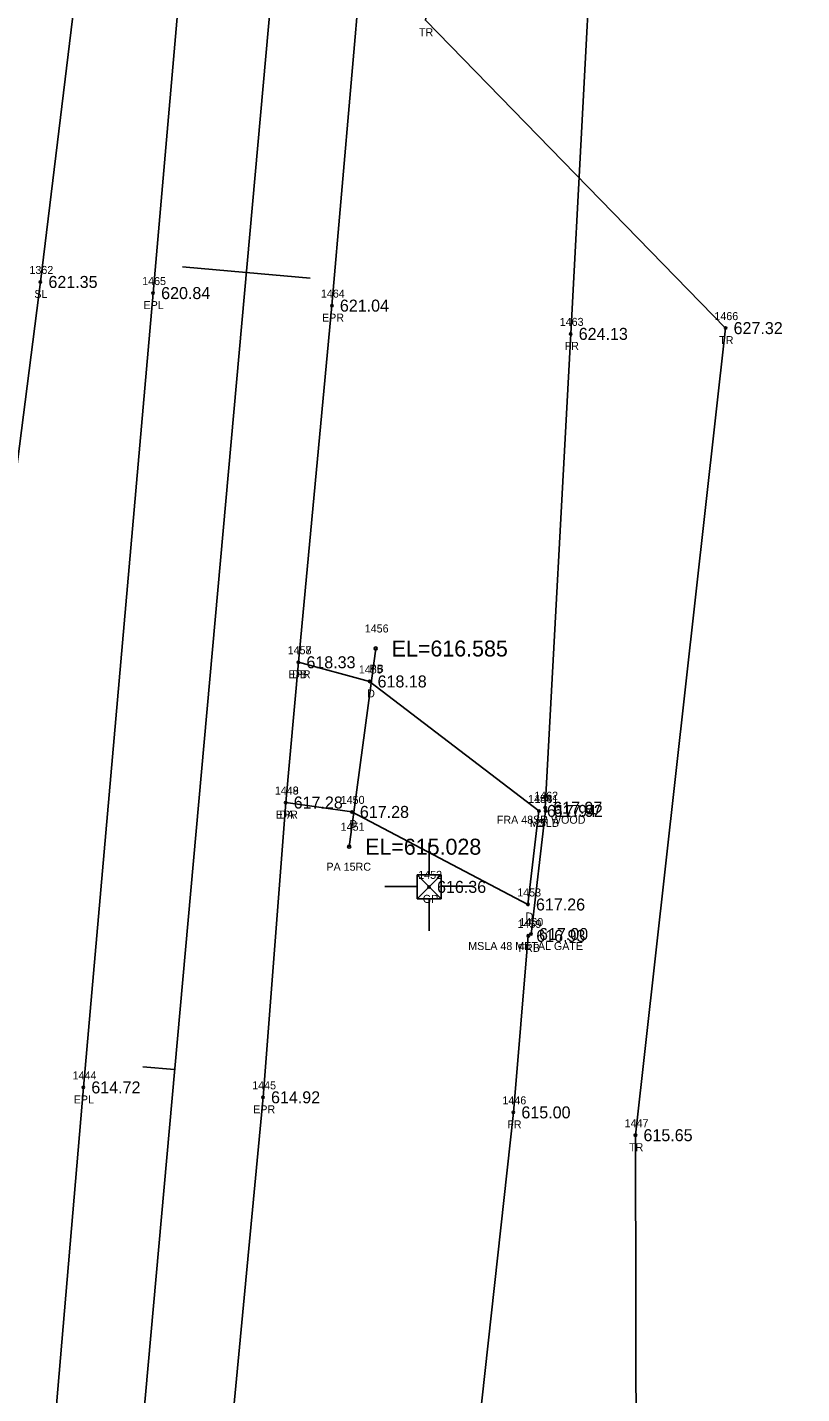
# Model space of a CAD drawing. Extents: x 1694813 to 1696862, y 1086485 to 1091027.
# Drawn here: x 1695817 to 1695913.8, y 1089981.5 to 1090152.3 of the extents above; entities that cross this region are included whole.
import ezdxf

# ---------------------------------------------------------------- set-up
doc = ezdxf.new("R2010")
doc.units = 0
for name, color, linetype in [('RD_EX_DR_Pipe', 7, 'Continuous'), ('RD_EX_DR_Pipe_txCode', 7, 'Continuous'), ('RD_EX_Driveway', 7, 'Continuous'), ('RD_EX_Driveway_txCode', 7, 'Continuous'), ('RD_EX_Fence_Other', 7, 'Continuous'), ('RD_EX_Fence_Other_txCode', 7, 'Continuous'), ('RD_EX_Misc', 7, 'Continuous'), ('RD_EX_Misc_txCode', 7, 'Continuous'), ('RD_EX_Road', 7, 'Continuous'), ('RD_EX_Road_txCode', 7, 'Continuous'), ('RD_EX_TX_Driveway_ELEV', 7, 'Continuous'), ('RD_EX_TX_Fence_Other_ELEV', 7, 'Continuous'), ('RD_EX_TX_Misc_ELEV', 7, 'Continuous'), ('RD_EX_TX_Road_ELEV', 7, 'Continuous'), ('RD_EX_TX_UT_ELEV', 7, 'Continuous'), ('RD_EX_TX_VEG_ELEV', 7, 'Continuous'), ('RD_EX_UT', 7, 'Continuous'), ('RD_EX_UT_txCode', 7, 'Continuous'), ('RD_EX_VEG', 7, 'Continuous'), ('RD_EX_VEG_txCode', 7, 'Continuous'), ('RD_HC_Cl', 7, 'Continuous'), ('RD_HC_Data_Tic', 7, 'Continuous'), ('RD_SMD_Locator', 7, 'Continuous'), ('RD_TX_Pipe_ElevEX', 7, 'Continuous')]:
    doc.layers.add(name, color=color, linetype=linetype)

msp = doc.modelspace()

# ---------------------------------------------------------------- linework, layer by layer
at = {"layer": 'RD_EX_DR_Pipe'}
msp.add_line((1695857.25, 1090049.87), (1695860.57, 1090074.64), dxfattribs=at)
at = {"layer": 'RD_EX_Driveway'}
msp.add_lwpolyline([(1695849.32, 1090055.39), (1695857.59, 1090054.22), (1695879.59, 1090042.65), (1695880.96, 1090054.34), (1695859.8, 1090070.52), (1695850.91, 1090072.92)], dxfattribs=at)
at = {"layer": 'RD_EX_Fence_Other'}
for points in [[(1695881.74, 1090054.74), (1695884.93, 1090113.96), (1695890.45, 1090217.67), (1695877.28, 1090215.01), (1695889.24, 1090305.77), (1695899.04, 1090409.63), (1695908.34, 1090511.05), (1695913.78, 1090608.15)], [(1695898.78, 1089833.45), (1695859, 1089834.26), (1695862.01, 1089865.39), (1695867.57, 1089916.68), (1695873.04, 1089973.43), (1695877.77, 1090016.67), (1695879.63, 1090038.73)]]:
    msp.add_lwpolyline(points, dxfattribs=at)
at = {"layer": 'RD_EX_Misc'}
msp.add_line((1695879.97, 1090038.96), (1695881.8, 1090054.35), dxfattribs=at)
at = {"layer": 'RD_EX_Road'}
for points in [[(1695813.78, 1089148.1), (1695805.56, 1089142.08), (1695776.44, 1089183.94), (1695749.27, 1089231.88), (1695730.49, 1089275.72), (1695714.87, 1089332.12), (1695707.87, 1089381.72), (1695706.58, 1089435.34), (1695711.58, 1089484.26), (1695722.15, 1089537.59), (1695749.04, 1089634.88), (1695776.11, 1089730.43), (1695788.13, 1089777.42), (1695798.89, 1089826.76), (1695807.1, 1089870.03), (1695814.71, 1089923.3), (1695820.51, 1089978.16), (1695824.04, 1090019.79), (1695832.76, 1090119.06), (1695841.25, 1090216.76), (1695850.36, 1090314.41), (1695859.24, 1090411.82), (1695868.09, 1090511.63), (1695876.75, 1090608.38)], [(1695735.35, 1089335.84), (1695728.69, 1089383.6), (1695727.9, 1089434.83), (1695732.68, 1089480.1), (1695743.4, 1089531.84), (1695770.35, 1089628.36), (1695797.63, 1089725.22), (1695809.49, 1089772.37), (1695818.34, 1089811.57), (1695820.65, 1089823.41), (1695822.99, 1089835.26), (1695829.18, 1089869.37), (1695836.32, 1089920.97), (1695842.44, 1089975.46), (1695846.49, 1090018.55), (1695849.32, 1090055.39), (1695850.91, 1090072.92), (1695855.09, 1090117.49), (1695863.53, 1090214.93), (1695872.56, 1090312.44), (1695881.69, 1090410.78), (1695890.45, 1090509.3), (1695899.01, 1090605.4)]]:
    msp.add_lwpolyline(points, dxfattribs=at)
at = {"layer": 'RD_EX_UT'}
for p, q in [((1695867.23, 1090046.35), (1695867.23, 1090050.35)), ((1695868.73, 1090046.35), (1695865.73, 1090043.35)), ((1695865.73, 1090046.35), (1695868.73, 1090043.35)), ((1695868.73, 1090046.35), (1695865.73, 1090046.35)), ((1695865.73, 1090046.35), (1695865.73, 1090043.35)), ((1695868.73, 1090043.35), (1695868.73, 1090046.35)), ((1695865.7, 1090044.9), (1695861.71, 1090044.9)), ((1695868.74, 1090044.92), (1695872.76, 1090044.92)), ((1695865.73, 1090043.35), (1695868.73, 1090043.35)), ((1695867.23, 1090043.35), (1695867.23, 1090039.35))]:
    msp.add_line(p, q, dxfattribs=at)
at = {"layer": 'RD_EX_VEG'}
for points in [[(1695885.82, 1089850.68), (1695893.09, 1089970.88), (1695893.02, 1090013.82), (1695904.28, 1090114.68), (1695866.77, 1090153.16), (1695876.29, 1090212.72), (1695880.67, 1090311.3), (1695888, 1090410.55), (1695898.84, 1090510.09), (1695910.81, 1090607.5)], [(1695762.44, 1089982.36), (1695791.84, 1089976.26), (1695804.67, 1089985.58), (1695805.61, 1090018.45), (1695818.68, 1090120.45), (1695830.78, 1090219.77), (1695838.1, 1090274.39)]]:
    msp.add_lwpolyline(points, dxfattribs=at)
at = {"layer": 'RD_HC_Cl'}
msp.add_line((1695830.5, 1089967.08), (1695888.3, 1090609.93), dxfattribs=at)
at = {"layer": 'RD_HC_Data_Tic'}
for p, q in [((1695844.4, 1090121.62), (1695836.43, 1090122.34)), ((1695844.4, 1090121.62), (1695852.36, 1090120.91)), ((1695835.44, 1090022.03), (1695831.46, 1090022.38))]:
    msp.add_line(p, q, dxfattribs=at)
at = {"layer": 'RD_SMD_Locator'}
for centre, radius in [((1695818.68, 1090120.45), 0.15), ((1695832.76, 1090119.06), 0.15), ((1695855.09, 1090117.49), 0.15), ((1695884.93, 1090113.96), 0.15), ((1695904.28, 1090114.68), 0.15), ((1695860.57, 1090074.64), 0.2), ((1695850.91, 1090072.92), 0.15), ((1695850.91, 1090072.92), 0.15), ((1695859.8, 1090070.52), 0.15), ((1695849.32, 1090055.39), 0.15), ((1695849.32, 1090055.39), 0.15), ((1695857.59, 1090054.22), 0.15), ((1695880.96, 1090054.34), 0.15), ((1695881.74, 1090054.74), 0.15), ((1695881.8, 1090054.35), 0.15), ((1695857.25, 1090049.87), 0.2), ((1695867.23, 1090044.85), 0.15), ((1695879.59, 1090042.65), 0.15), ((1695879.63, 1090038.73), 0.15), ((1695879.97, 1090038.96), 0.15), ((1695824.04, 1090019.79), 0.15), ((1695846.49, 1090018.55), 0.15), ((1695877.77, 1090016.67), 0.15), ((1695893.02, 1090013.82), 0.15)]:
    msp.add_circle(centre, radius, dxfattribs=at)

# ---------------------------------------------------------------- texts
at = {"layer": 'RD_EX_DR_Pipe_txCode'}
for s, p in [('1456', (1695859.2, 1090076.64)), ('PB', (1695859.79, 1090071.64)), ('1451', (1695856.19, 1090051.87)), ('PA 15RC', (1695854.41, 1090046.87))]:
    msp.add_text(s, height=1, dxfattribs=at).set_placement(p)
at = {"layer": 'RD_EX_Driveway_txCode'}
for s, p in [('1457', (1695849.57, 1090073.92)), ('DB', (1695850.13, 1090070.92)), ('1455', (1695858.46, 1090071.52)), ('D', (1695859.5, 1090068.52)), ('1449', (1695847.97, 1090056.39)), ('1450', (1695856.2, 1090055.22)), ('1454', (1695879.61, 1090055.34)), ('DA', (1695848.53, 1090053.39)), ('D', (1695857.28, 1090052.22)), ('D', (1695880.65, 1090052.34)), ('1453', (1695878.25, 1090043.65)), ('D', (1695879.29, 1090040.65))]:
    msp.add_text(s, height=1, dxfattribs=at).set_placement(p)
at = {"layer": 'RD_EX_Fence_Other_txCode'}
for s, p in [('1463', (1695883.56, 1090114.96)), ('FR', (1695884.17, 1090111.96)), ('1462', (1695880.37, 1090055.74)), ('FRA 48SR WOOD', (1695875.7, 1090052.74)), ('1459', (1695878.29, 1090039.73)), ('FRB', (1695878.4, 1090036.73)), ('1446', (1695876.4, 1090017.67)), ('FR', (1695877.01, 1090014.67))]:
    msp.add_text(s, height=1, dxfattribs=at).set_placement(p)
at = {"layer": 'RD_EX_Misc_txCode'}
for s, p in [('1461', (1695880.41, 1090055.35)), ('MSLB', (1695879.82, 1090052.35)), ('1460', (1695878.52, 1090039.96)), ('MSLA 48 METAL GATE', (1695872.13, 1090036.96))]:
    msp.add_text(s, height=1, dxfattribs=at).set_placement(p)
at = {"layer": 'RD_EX_Road_txCode'}
for s, p in [('1465', (1695831.39, 1090120.06)), ('1464', (1695853.72, 1090118.49)), ('EPL', (1695831.56, 1090117.06)), ('EPR', (1695853.86, 1090115.49)), ('1458', (1695849.57, 1090073.92)), ('EPR', (1695849.68, 1090070.92)), ('1448', (1695847.97, 1090056.39)), ('EPR', (1695848.09, 1090053.39)), ('1444', (1695822.7, 1090020.79)), ('1445', (1695845.14, 1090019.55)), ('EPL', (1695822.84, 1090017.79)), ('EPR', (1695845.26, 1090016.55))]:
    msp.add_text(s, height=1, dxfattribs=at).set_placement(p)
at = {"layer": 'RD_EX_TX_Driveway_ELEV'}
for s, p in [('618.33', (1695851.91, 1090072.17)), ('618.18', (1695860.8, 1090069.77)), ('617.28', (1695850.32, 1090054.64)), ('617.28', (1695858.59, 1090053.47)), ('617.94', (1695881.96, 1090053.59)), ('617.26', (1695880.59, 1090041.9))]:
    msp.add_text(s, height=1.5, dxfattribs=at).set_placement(p)
at = {"layer": 'RD_EX_TX_Fence_Other_ELEV'}
for s, p in [('624.13', (1695885.93, 1090113.21)), ('617.97', (1695882.74, 1090053.99)), ('616.93', (1695880.63, 1090037.98)), ('615.00', (1695878.77, 1090015.92))]:
    msp.add_text(s, height=1.5, dxfattribs=at).set_placement(p)
at = {"layer": 'RD_EX_TX_Misc_ELEV'}
for s, p in [('617.92', (1695882.8, 1090053.6)), ('617.00', (1695880.97, 1090038.21))]:
    msp.add_text(s, height=1.5, dxfattribs=at).set_placement(p)
at = {"layer": 'RD_EX_TX_Road_ELEV'}
for s, p in [('620.84', (1695833.76, 1090118.31)), ('621.04', (1695856.09, 1090116.74)), ('618.33', (1695851.91, 1090072.17)), ('617.28', (1695850.32, 1090054.64)), ('614.72', (1695825.04, 1090019.04)), ('614.92', (1695847.49, 1090017.8))]:
    msp.add_text(s, height=1.5, dxfattribs=at).set_placement(p)
at = {"layer": 'RD_EX_TX_UT_ELEV'}
msp.add_text('616.36', height=1.5, dxfattribs=at).set_placement((1695868.23, 1090044.1))
at = {"layer": 'RD_EX_TX_VEG_ELEV'}
for s, p in [('621.35', (1695819.68, 1090119.7)), ('627.32', (1695905.28, 1090113.93)), ('615.65', (1695894.02, 1090013.07))]:
    msp.add_text(s, height=1.5, dxfattribs=at).set_placement(p)
at = {"layer": 'RD_EX_UT_txCode'}
for s, p in [('1452', (1695865.88, 1090045.85)), ('GP', (1695866.45, 1090042.85))]:
    msp.add_text(s, height=1, dxfattribs=at).set_placement(p)
at = {"layer": 'RD_EX_VEG_txCode'}
for s, p in [('TR', (1695865.97, 1090151.16)), ('1362', (1695817.31, 1090121.45)), ('SL', (1695817.92, 1090118.45)), ('1466', (1695902.88, 1090115.68)), ('TR', (1695903.48, 1090112.68)), ('1447', (1695891.67, 1090014.82)), ('TR', (1695892.22, 1090011.82))]:
    msp.add_text(s, height=1, dxfattribs=at).set_placement(p)
at = {"layer": 'RD_TX_Pipe_ElevEX'}
for s, p in [('EL=616.585', (1695862.57, 1090073.64)), ('EL=615.028', (1695859.25, 1090048.87))]:
    msp.add_text(s, height=2, dxfattribs=at).set_placement(p)

doc.saveas('drawing.dxf')
